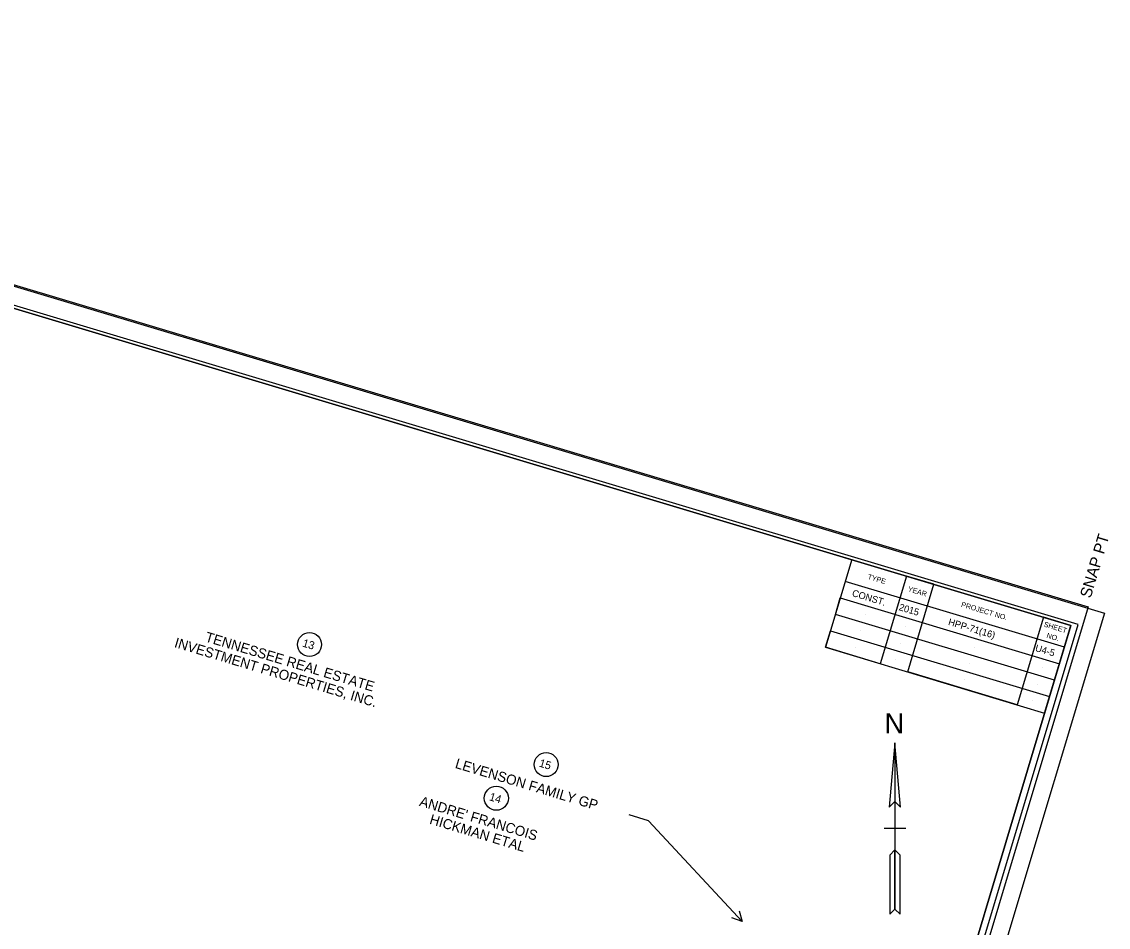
# Model space of a CAD drawing. Extents: x 2627582 to 2629622, y 568931 to 570612.
# Drawn here: x 2628672 to 2629622, y 569779 to 570571 of the extents above; entities that cross this region are included whole.
import ezdxf

# ---------------------------------------------------------------- set-up
doc = ezdxf.new("R2010")
doc.units = 0
for name, color, linetype in [('DESIGN - CENTERLINE - Proposed Text', 7, 'Continuous'), ('DESIGN - SCRATCH - User 1', 7, 'Continuous'), ('DESIGN - SHEET - Corner Text', 7, 'Continuous'), ('DESIGN - SHEET - Light Grid', 7, 'Continuous'), ('DESIGN - SHEET - Linework', 7, 'Continuous'), ('DESIGN - SHEET - Plot Shape', 7, 'Continuous'), ('SURVEY - PROPERTY - Owners', 7, 'Continuous'), ('SURVEY - PROPERTY - Tract Numbers', 7, 'Continuous')]:
    doc.layers.add(name, color=color, linetype=linetype)

msp = doc.modelspace()

# ---------------------------------------------------------------- linework, layer by layer
at = {"layer": 'DESIGN - CENTERLINE - Proposed Text'}
for p, q in [((2629435.34, 569865.62), (2629425.89, 569865.62)), ((2629444.79, 569865.62), (2629435.34, 569865.62))]:
    msp.add_line(p, q, dxfattribs=at)
msp.add_lwpolyline([(2629435.34, 569940.62), (2629430.44, 569884.32), (2629435.34, 569889.22), (2629440.24, 569884.32), (2629435.34, 569940.62), (2629435.34, 569795.17), (2629439.89, 569790.62), (2629439.89, 569842.37), (2629435.34, 569846.92), (2629430.79, 569842.37), (2629430.79, 569790.62), (2629435.34, 569795.17)], dxfattribs=at)
for points in [[(2629435.34, 569889.22), (2629440.24, 569884.32), (2629435.34, 569940.62)], [(2629430.79, 569790.62), (2629435.34, 569795.17), (2629435.34, 569846.92), (2629430.79, 569842.37)]]:
    msp.add_lwpolyline(points, close=True, dxfattribs=at)
at = {"layer": 'DESIGN - SCRATCH - User 1'}
for p, q in [((2629413.7, 570067.08), (2629413.7, 570067.08)), ((2629449.14, 570056.46), (2629449.14, 570056.46)), ((2629409.4, 570052.72), (2629409.4, 570052.72)), ((2629405.09, 570038.35), (2629405.09, 570038.35)), ((2629444.84, 570042.09), (2629444.84, 570042.09)), ((2629509.01, 570038.51), (2629509.01, 570038.51)), ((2629440.53, 570027.72), (2629440.53, 570027.72)), ((2629400.78, 570023.98), (2629400.78, 570023.98)), ((2629504.71, 570024.15), (2629504.71, 570024.15)), ((2629568.88, 570020.57), (2629568.88, 570020.57)), ((2629436.22, 570013.36), (2629436.22, 570013.36)), ((2629500.4, 570009.78), (2629500.4, 570009.78)), ((2629564.57, 570006.2), (2629564.57, 570006.2)), ((2629496.09, 569995.41), (2629496.09, 569995.41)), ((2629560.27, 569991.83), (2629560.27, 569991.83)), ((2629555.96, 569977.46), (2629555.96, 569977.46))]:
    msp.add_line(p, q, dxfattribs=at)
at = {"layer": 'DESIGN - SHEET - Light Grid'}
msp.add_lwpolyline([(2627697.64, 569511.43), (2629292.52, 569033.35), (2629595.46, 570043.92), (2628000.57, 570522.01)], close=True, dxfattribs=at)
at = {"layer": 'DESIGN - SHEET - Linework'}
for p, q in [((2627894.35, 570570.76), (2629618.55, 570053.91)), ((2629618.55, 570053.91), (2629306.31, 569012.3))]:
    msp.add_line(p, q, dxfattribs=at)
for points in [[(2628081.32, 570495.19), (2627779.83, 569489.41), (2629287.73, 569037.39), (2629589.23, 570043.18), (2628081.32, 570495.19)], [(2629397.65, 570100.61), (2629374.68, 570023.97), (2629566.26, 569966.55), (2629589.23, 570043.18), (2629565.28, 570050.36), (2629542.31, 569973.72), (2629446.52, 570002.44), (2629469.49, 570079.07), (2629445.55, 570086.25), (2629422.58, 570009.62), (2629374.68, 570023.97), (2629378.99, 570038.34), (2629570.57, 569980.91), (2629574.87, 569995.28), (2629383.29, 570052.71), (2629387.6, 570067.08), (2629579.18, 570009.65), (2629583.49, 570024.02), (2629391.91, 570081.45)]]:
    msp.add_lwpolyline(points, dxfattribs=at)
at = {"layer": 'DESIGN - SHEET - Plot Shape'}
for points in [[(2627975.91, 570547.35), (2629604.32, 570059.22), (2629291.51, 569015.7), (2627663.1, 569503.83)], [(2627999.85, 570519.61), (2629589.23, 570043.18), (2629287.73, 569037.39), (2627698.36, 569513.83)]]:
    msp.add_lwpolyline(points, close=True, dxfattribs=at)
at = {"layer": 'SURVEY - PROPERTY - Tract Numbers'}
for points in [[(2629219.73, 569872.44), (2629202.96, 569877.47)], [(2629301.81, 569784.18), (2629219.73, 569872.44)], [(2629299.05, 569793.57), (2629301.81, 569784.18), (2629292.65, 569787.61)]]:
    msp.add_lwpolyline(points, dxfattribs=at)
for centre in [(2628923.49, 570026.4), (2629130.39, 569921.48), (2629086.82, 569892.04)]:
    msp.add_circle(centre, 10.5, dxfattribs=at)

# ---------------------------------------------------------------- texts
at = {"layer": 'DESIGN - CENTERLINE - Proposed Text'}
msp.add_text('N', height=17.72, dxfattribs=at).set_placement((2629426.29, 569948.67))
at = {"layer": 'DESIGN - SHEET - Corner Text'}
for s, height, rotation, p in [('  SNAP PT', 10, 73.31329, (2629604.32, 570059.22)), ('TYPE', 4.5, 343.31329, (2629411.1, 570083.84)), ('CONST.', 6, 343.31329, (2629397.37, 570068.85)), ('YEAR', 4.5, 343.31329, (2629446.3, 570073.08)), ('PROJECT NO.', 4.5, 343.31329, (2629492.87, 570059.54)), ('2015', 6, 343.31329, (2629438.33, 570056.57)), ('HPP-71(16)', 6, 343.31329, (2629481.46, 570043.64)), ('SHEET', 4.5, 343.31329, (2629565.09, 570042.22)), ('NO.', 4.5, 343.31329, (2629567.52, 570032.41)), ('U4-5', 6, 343.31329, (2629557.5, 570020.85))]:
    msp.add_text(s, height=height, rotation=rotation, dxfattribs=at).set_placement(p)
at = {"layer": 'SURVEY - PROPERTY - Owners'}
for s, p in [('TENNESSEE REAL ESTATE', (2628831.6, 570029.26)), ('INVESTMENT PROPERTIES, INC.', (2628804.66, 570024.29)), ('LEVENSON FAMILY GP', (2629050.15, 569918.71)), ("ANDRE' FRANCOIS", (2629018.88, 569885.58)), ('HICKMAN ETAL', (2629027.76, 569869.87))]:
    msp.add_text(s, height=8.75, rotation=343.31329, dxfattribs=at).set_placement(p)
at = {"layer": 'SURVEY - PROPERTY - Tract Numbers'}
for s, p in [('13', (2628916.73, 570024.77)), ('15', (2629123.63, 569919.86)), ('14', (2629080.06, 569890.42))]:
    msp.add_text(s, height=7, rotation=343.31329, dxfattribs=at).set_placement(p)

doc.saveas('drawing.dxf')
